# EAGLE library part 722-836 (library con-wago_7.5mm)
Serie 722, Federleiste mit abgewinkelten Einlötstiften / Series 722, Female connector with angled solder pins Polzahl / Pole No.: 6 Rastermaß / Pitch: 7.5 mm Bemessungsspannung / Rated Voltage: 630 V Nennstrom / Nominal Current: 12 A Lötstiftlänge: / Solder Pin Length: 5 mm Farbe / Color: lichtgrau / light gray Stand: 01.01.2012. Die jeweils aktuellen Daten zu diesem Artikel finden Sie in unserem Produktkatalog, den Sie unter www.wago.com einsehen können. As of: 01/01/2012. Please find the newest data for this article in our product catalogue, which can be viewed under www.wago.com.
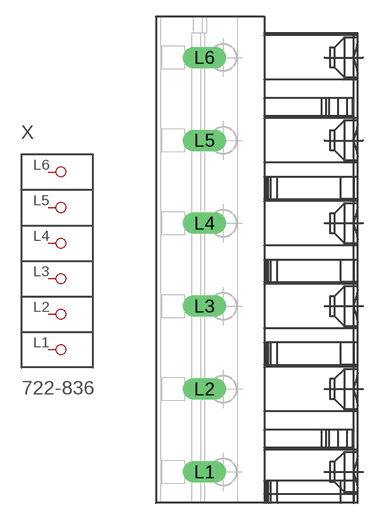
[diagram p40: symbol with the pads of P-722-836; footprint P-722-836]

Designator prefix X

## 722-836  [P-722-836]
L1  P1
L2  P2
L3  P3
L4  P4
L5  P5
L6  P6

## Footprint P-722-836 (pad centres in mm)
drill 1.3 long: L1 -4.973,-19.2; L2 -4.973,-11.7; L3 -4.973,-4.2; L4 -4.973,3.3; L5 -4.973,10.8; L6 -4.973,18.3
